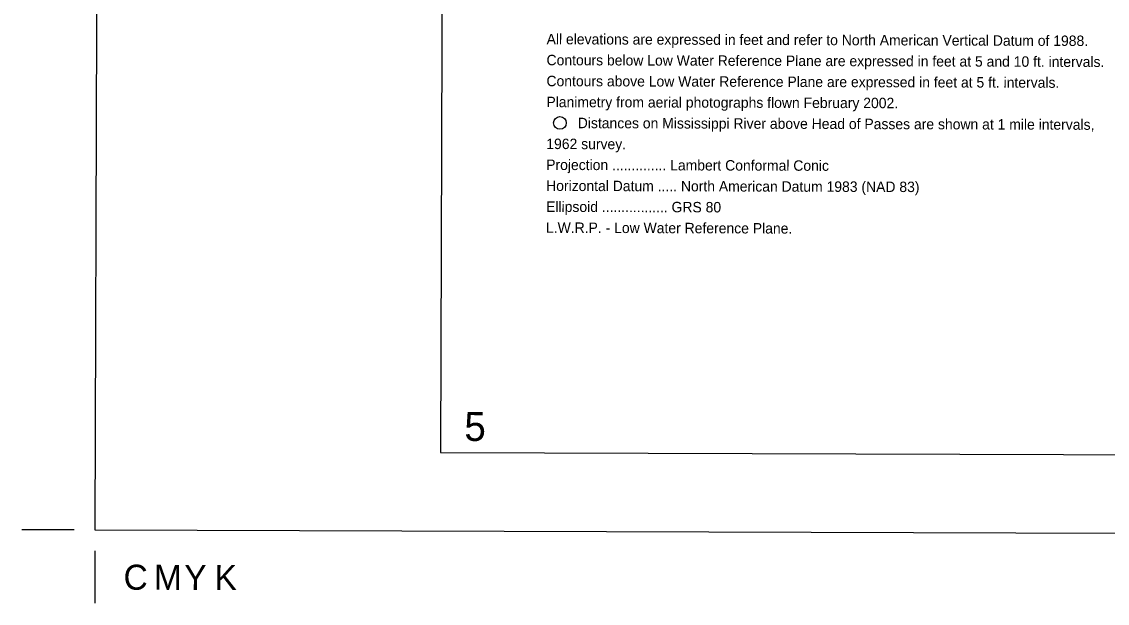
# Model space of a CAD drawing. Extents: x 3146026 to 3183936, y 897894 to 923344.
# Drawn here: x 3146026 to 3154671, y 898011 to 902639 of the extents above; entities that cross this region are included whole.
import ezdxf

# ---------------------------------------------------------------- set-up
doc = ezdxf.new("R2010")
doc.units = 0
for name, color, linetype in [('G-ANNO-NPLT', 7, 'Continuous'), ('V-ANNO-DIMS', 7, 'Continuous'), ('V-ANNO-NOTE', 7, 'Continuous'), ('V-ANNO-SYMB', 7, 'Continuous'), ('V-ANNO-TEXT', 7, 'Continuous')]:
    doc.layers.add(name, color=color, linetype=linetype)

msp = doc.modelspace()

# ---------------------------------------------------------------- linework, layer by layer
at = {"layer": 'G-ANNO-NPLT'}
msp.add_lwpolyline([(3146609.3, 898594.5), (3183275.8, 898477.1), (3183353.1, 922643.7), (3146686.6, 922761)], close=True, dxfattribs=at)
at = {"layer": 'V-ANNO-DIMS'}
for p, q in [((3146442.6, 898595), (3146026, 898596.3)), ((3146608.8, 898427.8), (3146607.4, 898011.1))]:
    msp.add_line(p, q, dxfattribs=at)
at = {"layer": 'V-ANNO-NOTE'}
msp.add_circle((3150312.1, 901834.1), 50, dxfattribs=at)
at = {"layer": 'V-ANNO-SYMB'}
msp.add_lwpolyline([(3149361.4, 899210.7), (3182444.4, 899104.8), (3182517.8, 922021.3), (3149434.7, 922127.2), (3149361.4, 899210.7)], dxfattribs=at)

# ---------------------------------------------------------------- texts
at = {"layer": 'V-ANNO-DIMS'}
for s, p in [('C', (3146836.7, 898119.1)), ('M', (3147078.4, 898118.3)), ('Y', (3147320.1, 898117.5)), ('K', (3147561.7, 898116.8))]:
    msp.add_text(s, height=199.3, rotation=359.81667, dxfattribs=at).set_placement(p)
at = {"layer": 'V-ANNO-NOTE'}
for s, rotation, p in [('All elevations are expressed in feet and refer to North American Vertical Datum of 1988.', 359.81667, (3150205.8, 902459.8)), ('Contours below Low Water Reference Plane are expressed in feet at 5 and 10 ft. intervals.', 359.81667, (3150205.3, 902293.1)), ('Contours above Low Water Reference Plane are expressed in feet at 5 ft. intervals.', 359.81667, (3150204.8, 902126.4)), ('Planimetry from aerial photographs flown February 2002.', 359.81667, (3150204.2, 901959.7)), ('Distances on Mississippi River above Head of Passes are shown at 1 mile intervals,', 359.81667, (3150453.9, 901792.2)), ('1962 survey.', 359.81667, (3150203.2, 901626.3)), ('Projection .............. Lambert Conformal Conic', 359.81664, (3150202.6, 901459.6)), ('Horizontal Datum ..... North American Datum 1983 (NAD 83)', 359.81664, (3150202.1, 901292.9)), ('Ellipsoid ................. GRS 80', 359.81664, (3150201.6, 901126.2)), ('L.W.R.P. - Low Water Reference Plane.', 359.81664, (3150201, 900959.5))]:
    msp.add_text(s, height=83, rotation=rotation, dxfattribs=at).set_placement(p)
at = {"layer": 'V-ANNO-TEXT'}
msp.add_text('5', height=230, rotation=359.81668, dxfattribs=at).set_placement((3149550.6, 899303.4))

doc.saveas('drawing.dxf')
